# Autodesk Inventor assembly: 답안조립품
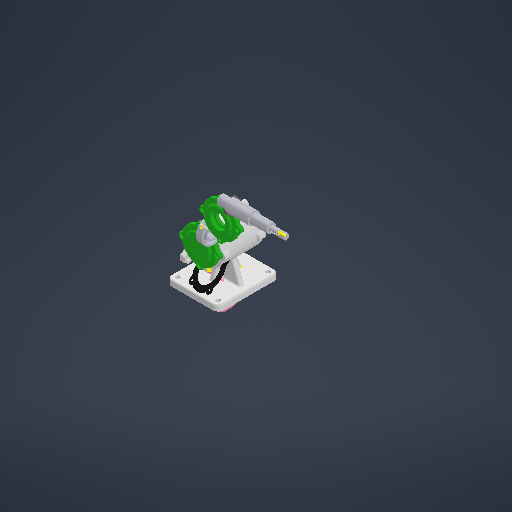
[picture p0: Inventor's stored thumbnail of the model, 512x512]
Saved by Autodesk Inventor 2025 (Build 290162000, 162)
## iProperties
Created: 2025-08
Part Number: 답안조립품
Document SubType Name: Assembly
Designer: infra012
Author: infra012
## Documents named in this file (12)
- C:\Users\infra012\Desktop\750806V1002\답안조립품.iam
- C:\Users\infra012\Desktop\750806V1002\V-벨트풀리\V-벨트풀리.ipt
- C:\Users\infra012\Desktop\750806V1002\개스킷\개스킷.ipt
- C:\Users\infra012\Desktop\750806V1002\너트 M12 x 1.25\너트 M12 x 1.25.ipt
- C:\Users\infra012\Desktop\750806V1002\뒤커버\뒤커버.ipt
- C:\Users\infra012\Desktop\750806V1002\베어링 6204\베어링 6204.ipt
- C:\Users\infra012\Desktop\750806V1002\볼트 M4 x 12\볼트 M4 x 12.ipt
- C:\Users\infra012\Desktop\750806V1002\앞커버\앞커버.ipt
- C:\Users\infra012\Desktop\750806V1002\오일 실\오일 실.ipt
- C:\Users\infra012\Desktop\750806V1002\축\축.ipt
- C:\Users\infra012\Desktop\750806V1002\키 4 x 4\키 4 x 4.ipt
- C:\Users\infra012\Desktop\750806V1002\본체.ipt
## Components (2 placed, 2 different names)
1. V-벨트풀리:1
2. 개스킷:1
